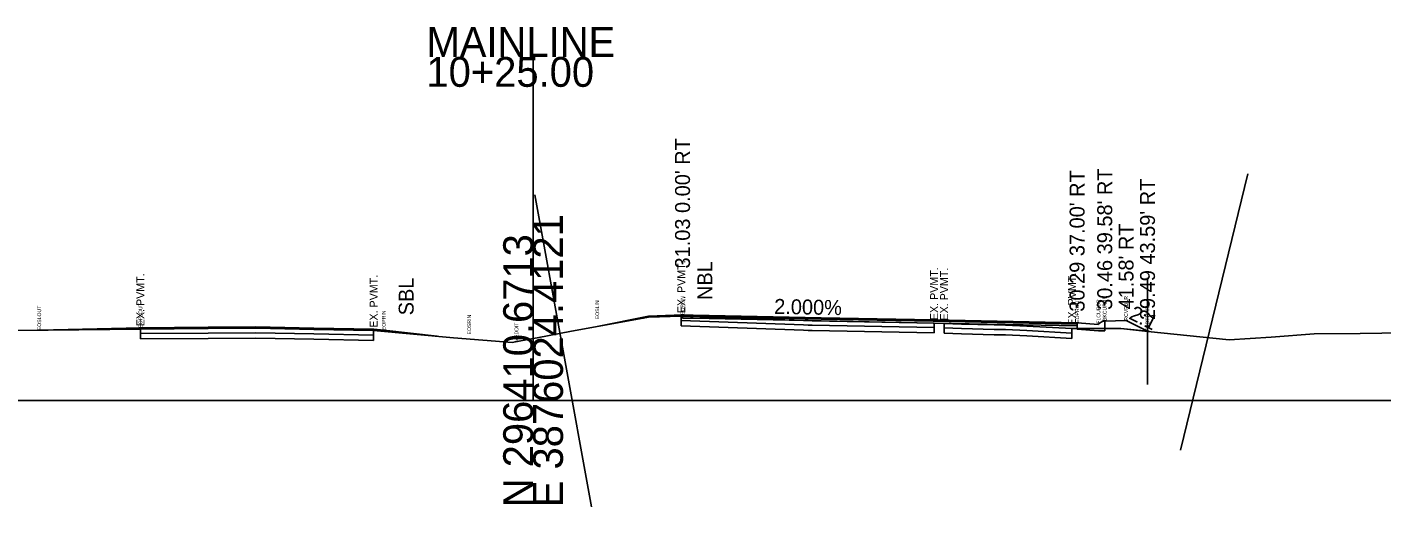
# Model space of a CAD drawing. Extents: x 14823 to 15251, y 114839 to 117377.
# Drawn here: x 15000.9 to 15127.9, y 115338.4 to 115383.4 of the extents above; entities that cross this region are included whole.
import ezdxf

# ---------------------------------------------------------------- set-up
doc = ezdxf.new("R2010")
doc.units = 0
for name, color, linetype in [('Default', 7, 'Continuous'), ('Level 1', 7, 'Continuous'), ('Level 10', 7, 'Continuous'), ('Level 11', 7, 'Continuous'), ('Level 2', 7, 'Continuous'), ('Level 25', 7, 'Continuous'), ('Level 3', 7, 'Continuous'), ('Level 4', 7, 'Continuous'), ('Level 42', 7, 'Continuous'), ('Level 49', 7, 'Continuous'), ('Level 50', 7, 'Continuous'), ('Level 52', 7, 'Continuous'), ('Level 53', 7, 'Continuous'), ('Level 56', 7, 'Continuous'), ('Level 59', 7, 'Continuous'), ('Level 63', 7, 'Continuous')]:
    doc.layers.add(name, color=color, linetype=linetype)

msp = doc.modelspace()

# ---------------------------------------------------------------- linework, layer by layer
at = {"layer": 'Default'}
for p, q in [((15115.36, 115369.64), (15109.05, 115343.71)), ((15048.53, 115367.65), (15053.85, 115338.39))]:
    msp.add_line(p, q, dxfattribs=at)
at = {"layer": 'Level 1'}
for p, q in [((15051.96, 115354.87), (15058.69, 115356.08)), ((15058.69, 115356.08), (15059.19, 115356.17)), ((15059.19, 115356.17), (15062.25, 115356.28)), ((15062.25, 115356.28), (15073.7, 115355.87)), ((14999.96, 115354.93), (15002.9, 115354.98)), ((15002.9, 115354.98), (15011.55, 115355.06)), ((15011.55, 115355.06), (15017.89, 115355.12)), ((15017.89, 115355.12), (15022.38, 115355.15)), ((15022.38, 115355.15), (15027.79, 115355.04)), ((15027.79, 115355.04), (15033.41, 115354.92)), ((15033.41, 115354.92), (15040.89, 115354.26)), ((15048.74, 115354.24), (15051.96, 115354.87)), ((15073.7, 115355.87), (15074.14, 115355.86)), ((15074.14, 115355.86), (15074.52, 115355.85)), ((15074.52, 115355.85), (15085.96, 115355.63)), ((15085.96, 115355.63), (15086.9, 115355.59)), ((15086.9, 115355.59), (15088.52, 115355.54)), ((15088.52, 115355.54), (15091.57, 115355.46)), ((15091.57, 115355.46), (15092.64, 115355.45)), ((15092.64, 115355.45), (15094.64, 115355.34)), ((15094.64, 115355.34), (15098.87, 115355.11)), ((15098.87, 115355.11), (15100.96, 115355.13)), ((15100.96, 115355.13), (15103.46, 115355.13)), ((15103.46, 115355.13), (15105.98, 115354.85)), ((15105.98, 115354.85), (15113.61, 115354.05)), ((15125.9, 115354.66), (15129.97, 115354.71)), ((15040.89, 115354.26), (15046.4, 115353.8)), ((15046.4, 115353.8), (15048.36, 115354.17)), ((15048.36, 115354.17), (15048.74, 115354.24)), ((15113.61, 115354.05), (15117.55, 115354.3)), ((15117.55, 115354.3), (15121.58, 115354.63)), ((15121.58, 115354.63), (15125.9, 115354.66))]:
    msp.add_line(p, q, dxfattribs=at)
at = {"layer": 'Level 10'}
for p, q in [((15059.19, 115356.17), (15059.19, 115356.29)), ((15062.37, 115356.27), (15062.37, 115356.39)), ((15062.37, 115356.1), (15062.37, 115356.27)), ((15062.37, 115356.27), (15063.36, 115356.25)), ((15062.37, 115356.1), (15063.36, 115356.08)), ((15075.36, 115356.01), (15063.36, 115356.25)), ((15075.36, 115355.84), (15063.36, 115356.08)), ((15085.86, 115355.8), (15075.36, 115356.01)), ((15034.36, 115354.97), (15034.36, 115354.84)), ((15085.86, 115355.63), (15075.36, 115355.84)), ((15085.86, 115355.8), (15099.36, 115355.53)), ((15085.86, 115355.63), (15099.36, 115355.36)), ((15099.36, 115355.53), (15099.36, 115355.65)), ((15099.36, 115355.36), (15099.36, 115355.53))]:
    msp.add_line(p, q, dxfattribs=at)
at = {"layer": 'Level 11'}
for p, q in [((15099.36, 115355.07), (15099.36, 115355.65)), ((15101.36, 115354.9), (15099.36, 115355.07)), ((15101.95, 115354.9), (15101.36, 115354.9)), ((15101.95, 115355.82), (15101.95, 115354.9))]:
    msp.add_line(p, q, dxfattribs=at)
at = {"layer": 'Level 2'}
for p, q in [((15059.19, 115356.29), (15062.37, 115356.39)), ((15062.37, 115356.39), (15063.36, 115356.37)), ((15063.36, 115356.37), (15075.36, 115356.13)), ((15075.36, 115356.13), (15085.86, 115355.92)), ((15011.55, 115355.19), (15002.07, 115354.96)), ((15011.55, 115355.19), (15017.89, 115355.24)), ((15017.89, 115355.24), (15022.38, 115355.27)), ((15022.38, 115355.27), (15027.79, 115355.16)), ((15027.79, 115355.16), (15033.42, 115355.05)), ((15033.42, 115355.05), (15034.36, 115354.97)), ((15085.86, 115355.92), (15099.36, 115355.65))]:
    msp.add_line(p, q, dxfattribs=at)
at = {"layer": 'Level 25'}
msp.add_line((15105.96, 115359.86), (15105.96, 115349.86), dxfattribs=at)
at = {"layer": 'Level 3'}
for p, q in [((15059.19, 115356.29), (15054.22, 115355.28)), ((15034.36, 115354.97), (15039.36, 115354.4)), ((15099.36, 115355.65), (15101.36, 115355.49)), ((15101.36, 115355.57), (15101.78, 115355.82)), ((15101.36, 115355.49), (15101.36, 115355.57)), ((15101.78, 115355.82), (15101.95, 115355.82))]:
    msp.add_line(p, q, dxfattribs=at)
at = {"layer": 'Level 4'}
for p, q in [((15101.95, 115355.82), (15103.95, 115355.86)), ((15103.95, 115355.86), (15105.96, 115354.86))]:
    msp.add_line(p, q, dxfattribs=at)
at = {"layer": 'Level 50'}
for points in [[(15062.37, 115356.39), (15063.36, 115356.37), (15075.36, 115356.13), (15085.86, 115355.92), (15099.36, 115355.65), (15099.36, 115355.11), (15098.87, 115355.11), (15094.64, 115355.34), (15092.64, 115355.45), (15091.57, 115355.46), (15088.52, 115355.54), (15086.9, 115355.59), (15085.96, 115355.63), (15074.52, 115355.85), (15074.14, 115355.86), (15073.7, 115355.87), (15062.25, 115356.28), (15059.19, 115356.17), (15058.69, 115356.08), (15054.22, 115355.28), (15059.19, 115356.29)], [(15062.37, 115356.39), (15063.36, 115356.37), (15075.36, 115356.13), (15085.86, 115355.92), (15099.36, 115355.65), (15099.36, 115355.11), (15098.87, 115355.11), (15094.64, 115355.34), (15092.64, 115355.45), (15091.57, 115355.46), (15088.52, 115355.54), (15086.9, 115355.59), (15085.96, 115355.63), (15074.52, 115355.85), (15074.14, 115355.86), (15073.7, 115355.87), (15062.25, 115356.28), (15059.19, 115356.17), (15058.69, 115356.08), (15054.22, 115355.28), (15059.19, 115356.29)], [(15101.95, 115354.9), (15101.36, 115354.9), (15099.36, 115355.07), (15099.36, 115355.11), (15100.96, 115355.13), (15101.95, 115355.13)], [(15101.95, 115354.9), (15101.36, 115354.9), (15099.36, 115355.07), (15099.36, 115355.11), (15100.96, 115355.13), (15101.95, 115355.13)], [(15101.95, 115355.82), (15103.95, 115355.86), (15105.96, 115354.86), (15103.46, 115355.13), (15101.95, 115355.13)], [(15101.95, 115355.82), (15103.95, 115355.86), (15105.96, 115354.86), (15103.46, 115355.13), (15101.95, 115355.13)]]:
    msp.add_lwpolyline(points, close=True, dxfattribs=at)
at = {"layer": 'Level 59'}
for p, q in [((15062.25, 115356.28), (15062.25, 115355.86)), ((15011.55, 115355.06), (15011.55, 115354.65)), ((15011.55, 115354.65), (15017.89, 115354.7)), ((15017.89, 115354.7), (15022.38, 115354.73)), ((15022.38, 115354.73), (15027.79, 115354.62)), ((15033.41, 115354.51), (15033.41, 115354.92)), ((15062.25, 115355.86), (15073.7, 115355.46)), ((15062.25, 115355.86), (15062.25, 115355.36)), ((15062.25, 115355.36), (15073.7, 115354.96)), ((15073.7, 115355.46), (15074.14, 115355.44)), ((15073.7, 115354.96), (15074.14, 115354.94)), ((15074.14, 115355.44), (15074.52, 115355.43)), ((15074.14, 115354.94), (15074.52, 115354.93)), ((15074.52, 115355.43), (15085.96, 115355.21)), ((15074.52, 115354.93), (15085.96, 115354.71)), ((15085.96, 115355.21), (15085.96, 115355.63)), ((15085.96, 115354.71), (15085.96, 115355.21)), ((15086.9, 115355.59), (15086.9, 115355.17)), ((15086.9, 115355.17), (15088.52, 115355.12)), ((15086.9, 115355.17), (15086.9, 115354.67)), ((15088.52, 115355.12), (15091.57, 115355.04)), ((15091.57, 115355.04), (15092.64, 115355.03)), ((15092.64, 115355.03), (15094.64, 115354.92)), ((15094.64, 115354.92), (15098.87, 115354.69)), ((15098.87, 115354.69), (15098.87, 115355.11)), ((15098.87, 115354.69), (15098.87, 115354.69)), ((15098.87, 115354.19), (15098.87, 115354.69)), ((15011.55, 115354.65), (15011.55, 115354.15)), ((15011.55, 115354.15), (15017.89, 115354.2)), ((15017.89, 115354.2), (15022.38, 115354.23)), ((15022.38, 115354.23), (15027.79, 115354.12)), ((15027.79, 115354.62), (15033.41, 115354.51)), ((15027.79, 115354.12), (15033.41, 115354.01)), ((15033.41, 115354.01), (15033.41, 115354.51)), ((15086.9, 115354.67), (15088.52, 115354.62)), ((15088.52, 115354.62), (15091.57, 115354.54)), ((15091.57, 115354.54), (15092.64, 115354.53)), ((15092.64, 115354.53), (15094.64, 115354.42)), ((15094.64, 115354.42), (15098.87, 115354.19)), ((15098.87, 115354.19), (15098.87, 115354.19))]:
    msp.add_line(p, q, dxfattribs=at)
at = {"layer": 'Level 63'}
for p, q in [((15048.36, 115348.36), (15048.36, 115380.59)), ((14848.36, 115348.36), (15048.36, 115348.36)), ((15048.36, 115348.36), (15248.36, 115348.36))]:
    msp.add_line(p, q, dxfattribs=at)

# ---------------------------------------------------------------- texts
at = {"layer": 'Level 42'}
for s, p in [('NBL', (15065.16, 115357.79)), ('SBL', (15037.16, 115356.36))]:
    msp.add_text(s, height=1.4, rotation=90, dxfattribs=at).set_placement(p)
at = {"layer": 'Level 49'}
msp.add_text('2.000%', height=1.4, rotation=358.8542, dxfattribs=at).set_placement((15070.95, 115356.5))
at = {"layer": 'Level 50'}
msp.add_text('2:1', height=1.4, rotation=333.435, dxfattribs=at).set_placement((15104.13, 115356.08))
at = {"layer": 'Level 52'}
for s, p in [("31.03 0.00' RT", (15063.07, 115360.75)), ("30.46 39.58' RT", (15102.65, 115356.87)), ("30.29 37.00' RT", (15100.06, 115356.7)), ("29.49 43.59' RT", (15106.66, 115355.91)), ("41.58' RT", (15104.65, 115356.91))]:
    msp.add_text(s, height=1.4, rotation=90, dxfattribs=at).set_placement(p)
at = {"layer": 'Level 53'}
for p in [(15062.63, 115356.28), (15011.92, 115355.06), (15033.79, 115354.92), (15086.33, 115355.63), (15087.27, 115355.59), (15099.25, 115355.11)]:
    msp.add_text(' EX. PVMT.', height=0.75, rotation=90, dxfattribs=at).set_placement(p)
at = {"layer": 'Level 56'}
for s, p in [('EOPLOUT', (15011.72, 115355.19)), ('EOSLIN', (15054.55, 115355.99)), ('EOPLIN', (15062.55, 115356.39)), ('EOPROUT', (15099.54, 115355.65)), ('FLCURBR', (15101.54, 115355.57)), ('BKCURBR', (15102.12, 115355.82)), ('RCVRBLR', (15104.12, 115355.86)), ('EOSLOUT', (15002.24, 115354.96)), ('EOPRIN', (15034.54, 115354.96)), ('EOSRIN', (15042.54, 115354.56)), ('FRDTCHR', (15106.13, 115354.86)), ('MEDDIT', (15046.97, 115353.83))]:
    msp.add_text(s, height=0.35, rotation=90, dxfattribs=at).set_placement(p)
at = {"layer": 'Level 63'}
for s, p in [('MAINLINE', (15038.37, 115380.59)), ('10+25.00', (15038.36, 115377.79))]:
    msp.add_text(s, height=2.8, dxfattribs=at).set_placement(p)
for s, p in [('E 3876024.4121', (15051.16, 115338.36)), ('N 296410.6713', (15048.36, 115338.36))]:
    msp.add_text(s, height=2.8, rotation=90, dxfattribs=at).set_placement(p)

doc.saveas('drawing.dxf')
